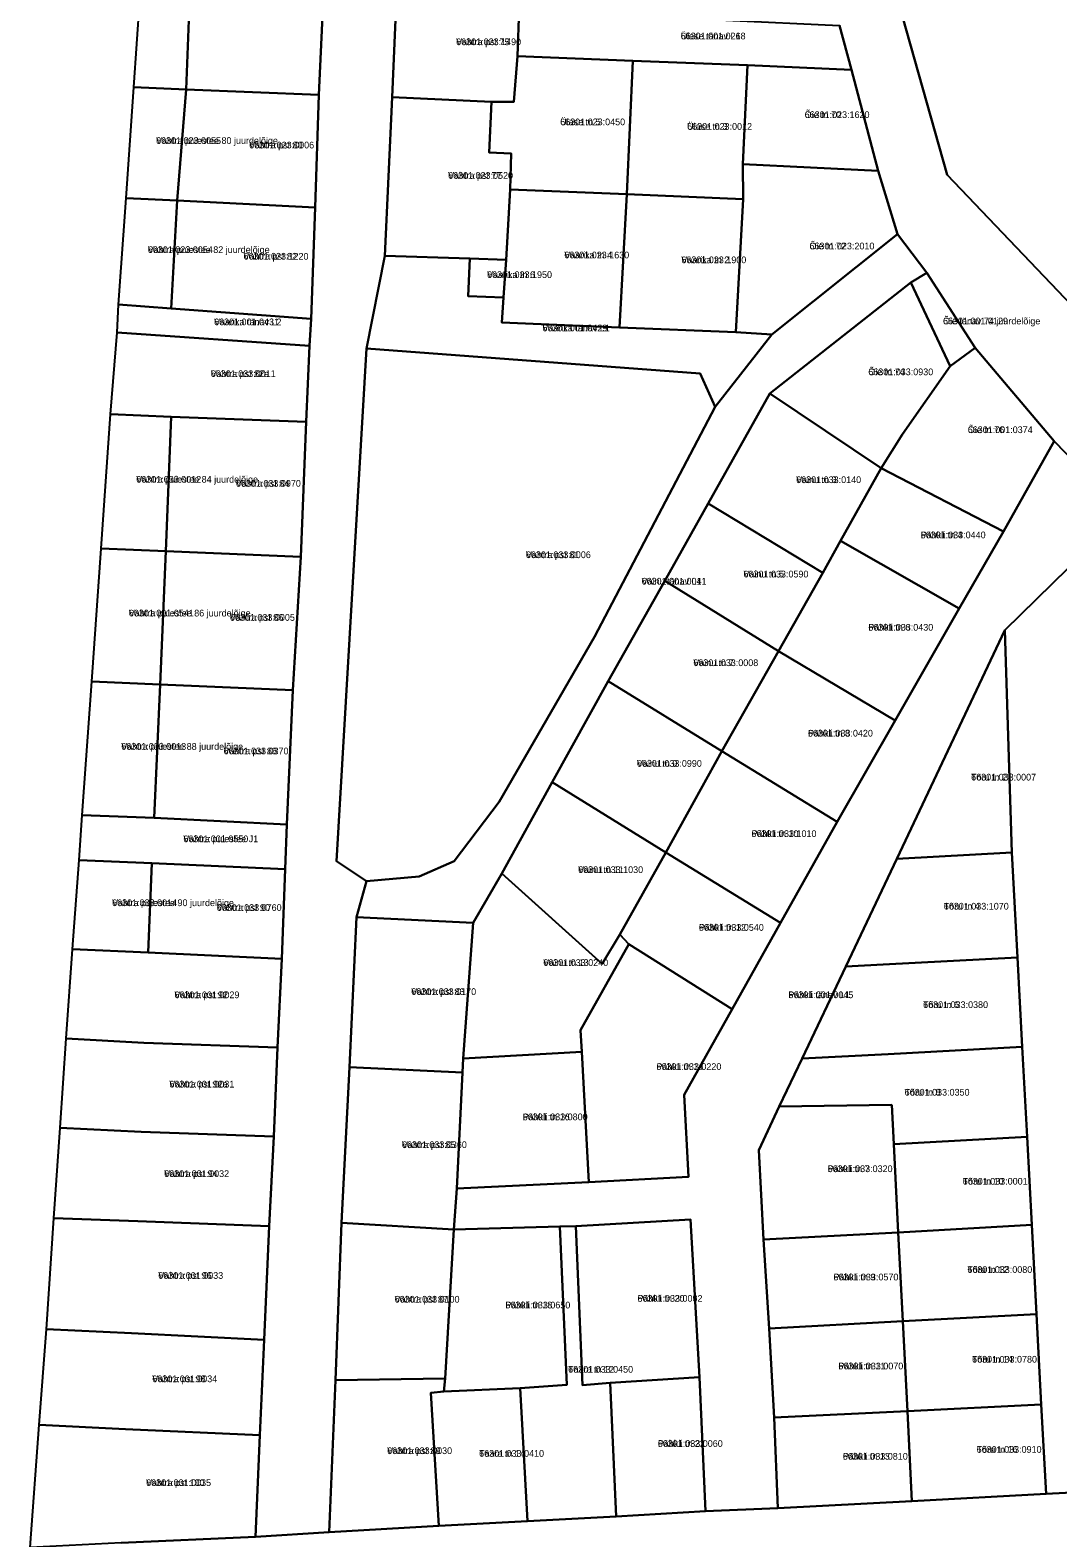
# Model space of a CAD drawing. Extents: x 632278 to 636344, y 6578401 to 6583362.
# Drawn here: x 633418.1 to 633647.7, y 6579191.1 to 6579527.9 of the extents above; entities that cross this region are included whole.
import ezdxf

# ---------------------------------------------------------------- set-up
doc = ezdxf.new("R2010")
doc.units = 0
for name, color, linetype in [('L_AADRESS', 7, 'Continuous'), ('PIIR', 7, 'Continuous'), ('TUNNUS', 7, 'Continuous')]:
    doc.layers.add(name, color=color, linetype=linetype)

msp = doc.modelspace()

# ---------------------------------------------------------------- linework, layer by layer
at = {"layer": 'PIIR'}
for points in [[(633731.62, 6579938.95), (633729.12, 6579898.18), (633727.06, 6579864.84), (633761.13, 6579852.59), (633767.01, 6579845.53), (633761.47, 6579821.43), (633754.84, 6579796.9), (633742.28, 6579739.12), (633736.02, 6579694.18), (633729.46, 6579605.05), (633719.19, 6579444.37), (633716.61, 6579430.7), (633712.76, 6579423.18), (633706.21, 6579417.63), (633697.14, 6579417.83), (633622.95, 6579495.56), (633611.14, 6579537.54), (633608.35, 6579581.69), (633605.51, 6579809.61), (633653.33, 6579978.24)], [(633500.02, 6579537.22), (633499.02, 6579512.94), (633497.4, 6579477.46), (633493.24, 6579456.8), (633486.56, 6579342.26), (633493.24, 6579337.75), (633491.03, 6579329.74), (633489.47, 6579296.23), (633487.68, 6579261.45), (633486.36, 6579226.34), (633484.92, 6579192.34), (633468.5, 6579191.32), (633469.42, 6579214.02), (633470.42, 6579235.35), (633471.5, 6579260.74), (633472.58, 6579280.76), (633473.39, 6579300.65), (633474.39, 6579320.44), (633475.08, 6579340.46), (633475.51, 6579350.45), (633476.83, 6579380.42), (633478.58, 6579410.22), (633479.79, 6579440.42), (633480.52, 6579457.36), (633480.9, 6579463.43), (633481.79, 6579488.29), (633482.64, 6579513.43), (633483.95, 6579542.35)], [(633611.14, 6579537.54), (633622.95, 6579495.56), (633697.14, 6579417.83), (633718.97, 6579394.93), (633711.9, 6579377.45), (633668.34, 6579418), (633662.27, 6579420.21), (633646.91, 6579436.06), (633629.25, 6579456.91), (633618.44, 6579473.7), (633611.88, 6579482.28), (633607.54, 6579496.46), (633601.63, 6579519.02), (633598.91, 6579528.9)], [(633650.04, 6579407.66), (633635.87, 6579393.82), (633611.74, 6579342.8), (633600.33, 6579318.69), (633590.6, 6579298.13), (633585.47, 6579287.42), (633580.93, 6579277.69), (633581.99, 6579257.71), (633583.2, 6579237.88), (633584.33, 6579217.94), (633585.14, 6579197.71), (633569, 6579197.03), (633567.65, 6579226.96), (633565.62, 6579262.21), (633540, 6579260.71), (633536.46, 6579260.63), (633512.76, 6579259.93), (633513.44, 6579269.1), (633542.91, 6579270.56), (633565.18, 6579271.75), (633564.21, 6579290.03), (633574.98, 6579309.21), (633585.77, 6579328.49), (633598.42, 6579351.03), (633611.36, 6579373.69), (633625.65, 6579398.67), (633635.54, 6579415.92), (633644.47, 6579431.82), (633646.91, 6579436.06), (633662.27, 6579420.21)], [(633438.5, 6579189.98), (633468.5, 6579191.32), (633484.92, 6579192.34), (633509.41, 6579193.75), (633529.26, 6579194.83), (633549.02, 6579195.85), (633569, 6579197.03), (633585.14, 6579197.71), (633615.1, 6579199.3), (633645.06, 6579200.89), (633661.04, 6579201.74), (633691, 6579203.33), (633720.95, 6579204.91), (633722.5, 6579190.62)]]:
    msp.add_lwpolyline(points, dxfattribs=at)
for points in [[(633443.32, 6579544.24), (633454.12, 6579543.73), (633452.98, 6579514.62), (633441.32, 6579515.15)], [(633454.12, 6579543.73), (633483.95, 6579542.35), (633482.64, 6579513.43), (633452.98, 6579514.62)], [(633500.02, 6579537.22), (633527.61, 6579536.52), (633527.39, 6579532.61), (633527.01, 6579522.04), (633526.21, 6579511.86), (633521.18, 6579511.84), (633499.02, 6579512.94)], [(633527.39, 6579532.61), (633550.35, 6579531.56), (633573.55, 6579530.08), (633598.91, 6579528.9), (633601.63, 6579519.02), (633578.37, 6579520.03), (633552.77, 6579521.04), (633527.01, 6579522.04)], [(633551.41, 6579491.24), (633525.35, 6579492.32), (633525.6, 6579500.36), (633520.71, 6579500.58), (633521.18, 6579511.84), (633526.21, 6579511.86), (633527.01, 6579522.04), (633552.77, 6579521.04)], [(633552.77, 6579521.04), (633578.37, 6579520.03), (633577.36, 6579497.94), (633577.39, 6579490.16), (633551.41, 6579491.24)], [(633601.63, 6579519.02), (633607.54, 6579496.46), (633577.36, 6579497.94), (633578.37, 6579520.03)], [(633441.32, 6579515.15), (633452.98, 6579514.62), (633450.97, 6579489.8), (633439.57, 6579490.33)], [(633450.97, 6579489.8), (633452.98, 6579514.62), (633482.64, 6579513.43), (633481.79, 6579488.29)], [(633499.02, 6579512.94), (633521.18, 6579511.84), (633520.71, 6579500.58), (633525.6, 6579500.36), (633525.35, 6579492.32), (633524.46, 6579476.6), (633516.32, 6579476.86), (633497.4, 6579477.46)], [(633575.79, 6579460.41), (633577.39, 6579490.16), (633577.36, 6579497.94), (633607.54, 6579496.46), (633611.88, 6579482.28), (633583.78, 6579459.87)], [(633523.9, 6579468.14), (633524.46, 6579476.6), (633525.35, 6579492.32), (633551.41, 6579491.24), (633549.82, 6579461.47), (633523.52, 6579462.54)], [(633439.57, 6579490.33), (633450.97, 6579489.8), (633449.66, 6579465.71), (633437.88, 6579466.57)], [(633449.66, 6579465.71), (633450.97, 6579489.8), (633481.79, 6579488.29), (633480.9, 6579463.43)], [(633551.41, 6579491.24), (633577.39, 6579490.16), (633575.79, 6579460.41), (633549.82, 6579461.47)], [(633611.88, 6579482.28), (633618.44, 6579473.7), (633614.85, 6579471.54), (633583.37, 6579446.75), (633569.58, 6579422.13), (633559.93, 6579404.83), (633547.23, 6579382.48), (633534.77, 6579359.89), (633523.52, 6579339.5), (633517.08, 6579328.49), (633491.03, 6579329.74), (633493.24, 6579337.75), (633505.06, 6579338.83), (633512.83, 6579342.26), (633522.93, 6579355.47), (633544.22, 6579392.32), (633571.19, 6579443.74), (633583.78, 6579459.87)], [(633497.4, 6579477.46), (633516.32, 6579476.86), (633515.96, 6579468.46), (633523.9, 6579468.14), (633523.52, 6579462.54), (633549.82, 6579461.47), (633575.79, 6579460.41), (633583.78, 6579459.87), (633571.19, 6579443.74), (633567.77, 6579451.21), (633493.24, 6579456.8)], [(633516.32, 6579476.86), (633524.46, 6579476.6), (633523.9, 6579468.14), (633515.96, 6579468.46)], [(633608.26, 6579430.06), (633583.37, 6579446.75), (633614.85, 6579471.54), (633623.64, 6579452.85), (633613, 6579437.61)], [(633614.85, 6579471.54), (633618.44, 6579473.7), (633629.25, 6579456.91), (633623.64, 6579452.85)], [(633437.88, 6579466.57), (633449.66, 6579465.71), (633480.9, 6579463.43), (633480.52, 6579457.36), (633437.55, 6579460.36)], [(633480.52, 6579457.36), (633479.79, 6579440.42), (633449.65, 6579441.53), (633436.08, 6579442.07), (633437.55, 6579460.36)], [(633493.24, 6579456.8), (633567.77, 6579451.21), (633571.19, 6579443.74), (633544.22, 6579392.32), (633522.93, 6579355.47), (633512.83, 6579342.26), (633505.06, 6579338.83), (633493.24, 6579337.75), (633486.56, 6579342.26)], [(633623.64, 6579452.85), (633629.25, 6579456.91), (633646.91, 6579436.06), (633644.47, 6579431.82), (633635.54, 6579415.92), (633608.26, 6579430.06), (633613, 6579437.61)], [(633608.26, 6579430.06), (633599.17, 6579413.79), (633595.18, 6579406.65), (633569.58, 6579422.13), (633583.37, 6579446.75)], [(633436.08, 6579442.07), (633449.65, 6579441.53), (633448.42, 6579411.46), (633434.02, 6579412.07)], [(633448.42, 6579411.46), (633449.65, 6579441.53), (633479.79, 6579440.42), (633478.58, 6579410.22)], [(633608.26, 6579430.06), (633635.54, 6579415.92), (633625.65, 6579398.67), (633599.17, 6579413.79)], [(633569.58, 6579422.13), (633595.18, 6579406.65), (633585.32, 6579389.12), (633559.93, 6579404.83)], [(633448.42, 6579411.46), (633447.21, 6579381.68), (633431.94, 6579382.38), (633434.02, 6579412.07)], [(633448.42, 6579411.46), (633478.58, 6579410.22), (633476.83, 6579380.42), (633447.21, 6579381.68)], [(633595.18, 6579406.65), (633599.17, 6579413.79), (633625.65, 6579398.67), (633611.36, 6579373.69), (633585.32, 6579389.12)], [(633635.87, 6579393.82), (633650.04, 6579407.66), (633650.83, 6579391.32), (633652.84, 6579361.34), (633654.02, 6579341.46), (633654.99, 6579321.67), (633656.02, 6579301.75), (633656.78, 6579281.63), (633657.84, 6579261.66), (633658.91, 6579241.68), (633659.97, 6579221.71), (633661.04, 6579201.74), (633645.06, 6579200.89), (633644, 6579220.86), (633642.96, 6579241.06), (633641.89, 6579261.03), (633640.82, 6579280.65), (633639.73, 6579300.75), (633638.67, 6579320.73), (633637.42, 6579344.17)], [(633559.93, 6579404.83), (633585.32, 6579389.12), (633572.61, 6579366.8), (633547.23, 6579382.48)], [(633635.87, 6579393.82), (633637.42, 6579344.17), (633611.74, 6579342.8)], [(633611.36, 6579373.69), (633598.42, 6579351.03), (633572.61, 6579366.8), (633585.32, 6579389.12)], [(633431.94, 6579382.38), (633447.21, 6579381.68), (633445.87, 6579351.89), (633429.78, 6579352.5)], [(633476.83, 6579380.42), (633475.51, 6579350.45), (633445.87, 6579351.89), (633447.21, 6579381.68)], [(633547.23, 6579382.48), (633572.61, 6579366.8), (633560.11, 6579344.16), (633534.77, 6579359.89)], [(633572.61, 6579366.8), (633598.42, 6579351.03), (633585.77, 6579328.49), (633560.11, 6579344.16)], [(633549.83, 6579325.87), (633545.91, 6579319.3), (633523.52, 6579339.5), (633534.77, 6579359.89), (633560.11, 6579344.16)], [(633475.51, 6579350.45), (633475.08, 6579340.46), (633445.31, 6579341.82), (633429.11, 6579342.49), (633429.78, 6579352.5), (633445.87, 6579351.89)], [(633549.83, 6579325.87), (633560.11, 6579344.16), (633585.77, 6579328.49), (633574.98, 6579309.21), (633551.87, 6579323.69)], [(633600.33, 6579318.69), (633611.74, 6579342.8), (633637.42, 6579344.17), (633638.67, 6579320.73), (633608.71, 6579319.13)], [(633429.11, 6579342.49), (633445.31, 6579341.82), (633444.47, 6579321.86), (633427.59, 6579322.62)], [(633445.31, 6579341.82), (633475.08, 6579340.46), (633474.39, 6579320.44), (633444.47, 6579321.86)], [(633517.08, 6579328.49), (633523.52, 6579339.5), (633545.91, 6579319.3), (633549.83, 6579325.87), (633551.87, 6579323.69), (633541.1, 6579304.51), (633541.36, 6579299.63), (633514.9, 6579298.17)], [(633514.9, 6579298.17), (633514.68, 6579295.03), (633489.47, 6579296.23), (633491.03, 6579329.74), (633517.08, 6579328.49)], [(633541.36, 6579299.63), (633541.1, 6579304.51), (633551.87, 6579323.69), (633574.98, 6579309.21), (633564.21, 6579290.03), (633565.18, 6579271.75), (633542.91, 6579270.56)], [(633426.18, 6579302.6), (633427.59, 6579322.62), (633444.47, 6579321.86), (633474.39, 6579320.44), (633473.39, 6579300.65), (633443.57, 6579301.66)], [(633590.6, 6579298.13), (633600.33, 6579318.69), (633608.71, 6579319.13), (633638.67, 6579320.73), (633639.73, 6579300.75), (633609.77, 6579299.16)], [(633424.86, 6579282.64), (633426.18, 6579302.6), (633443.57, 6579301.66), (633473.39, 6579300.65), (633472.58, 6579280.76), (633442.93, 6579281.75)], [(633514.68, 6579295.03), (633514.9, 6579298.17), (633541.36, 6579299.63), (633542.91, 6579270.56), (633513.44, 6579269.1)], [(633610.63, 6579287.84), (633585.47, 6579287.42), (633590.6, 6579298.13), (633609.77, 6579299.16), (633639.73, 6579300.75), (633640.82, 6579280.65), (633611.09, 6579278.99)], [(633489.47, 6579296.23), (633514.68, 6579295.03), (633513.44, 6579269.1), (633512.76, 6579259.93), (633487.68, 6579261.45)], [(633610.63, 6579287.84), (633611.09, 6579278.99), (633612.01, 6579259.3), (633581.99, 6579257.71), (633580.93, 6579277.69), (633585.47, 6579287.42)], [(633423.4, 6579262.52), (633424.86, 6579282.64), (633442.93, 6579281.75), (633472.58, 6579280.76), (633471.5, 6579260.74), (633442.18, 6579261.8)], [(633640.82, 6579280.65), (633641.89, 6579261.03), (633612.01, 6579259.3), (633611.09, 6579278.99)], [(633421.78, 6579237.68), (633423.4, 6579262.52), (633442.18, 6579261.8), (633471.5, 6579260.74), (633470.42, 6579235.35), (633440.78, 6579236.78)], [(633487.68, 6579261.45), (633512.76, 6579259.93), (633510.86, 6579226.68), (633486.36, 6579226.34)], [(633510.86, 6579226.68), (633512.76, 6579259.93), (633536.46, 6579260.63), (633538.03, 6579225.24), (633527.61, 6579224.52), (633510.57, 6579223.8)], [(633527.61, 6579224.52), (633538.03, 6579225.24), (633536.46, 6579260.63), (633540, 6579260.71), (633541.52, 6579225.17), (633547.7, 6579225.74), (633549.02, 6579195.85), (633529.26, 6579194.83)], [(633565.62, 6579262.21), (633567.65, 6579226.96), (633547.7, 6579225.74), (633541.52, 6579225.17), (633540, 6579260.71)], [(633581.99, 6579257.71), (633612.01, 6579259.3), (633613.11, 6579239.48), (633583.2, 6579237.88)], [(633612.01, 6579259.3), (633641.89, 6579261.03), (633642.96, 6579241.06), (633613.11, 6579239.48)], [(633613.11, 6579239.48), (633614.11, 6579219.38), (633584.33, 6579217.94), (633583.2, 6579237.88)], [(633613.11, 6579239.48), (633642.96, 6579241.06), (633644, 6579220.86), (633614.11, 6579219.38)], [(633420.14, 6579216.36), (633421.78, 6579237.68), (633440.78, 6579236.78), (633470.42, 6579235.35), (633469.42, 6579214.02), (633439.45, 6579215.39)], [(633486.36, 6579226.34), (633510.86, 6579226.68), (633510.57, 6579223.8), (633507.61, 6579223.5), (633509.41, 6579193.75), (633484.92, 6579192.34)], [(633567.65, 6579226.96), (633569, 6579197.03), (633549.02, 6579195.85), (633547.7, 6579225.74)], [(633507.61, 6579223.5), (633510.57, 6579223.8), (633527.61, 6579224.52), (633529.26, 6579194.83), (633509.41, 6579193.75)], [(633584.33, 6579217.94), (633614.11, 6579219.38), (633615.1, 6579199.3), (633585.14, 6579197.71)], [(633614.11, 6579219.38), (633644, 6579220.86), (633645.06, 6579200.89), (633615.1, 6579199.3)], [(633418.14, 6579188.93), (633420.14, 6579216.36), (633439.45, 6579215.39), (633469.42, 6579214.02), (633468.5, 6579191.32), (633438.5, 6579189.98)]]:
    msp.add_lwpolyline(points, close=True, dxfattribs=at)

# ---------------------------------------------------------------- texts
at = {"layer": 'L_AADRESS'}
for s, p in [('Vahtra pst 75', (633513.3, 6579524.53)), ('Ülase tänav L1', (633563.45, 6579525.82)), ('Ülase tn 5', (633536.54, 6579506.64)), ('Õie tn 70', (633591.14, 6579508.25)), ('Ülase tn 3', (633564.89, 6579505.62)), ('Vahtra puiestee 80 juurdelõige', (633446.27, 6579502.47)), ('Vahtra pst 80', (633467.07, 6579501.46)), ('Vahtra pst 77', (633511.5, 6579494.67)), ('Vahtra puiestee 82 juurdelõige', (633444.43, 6579478.1)), ('Vahtra pst 82', (633465.81, 6579476.62)), ('Vaarika tn 4', (633537.46, 6579476.9)), ('Õie tn 72', (633592.22, 6579478.91)), ('Vaarika tn 2', (633563.61, 6579475.82)), ('Vaarika tn 6', (633520.21, 6579472.51)), ('Vaarika tänav L2', (633459.22, 6579461.96)), ('Vaarika tänav L1', (633532.57, 6579460.6)), ('Õie tänav 74 juurdelõige', (633622.05, 6579462.16)), ('Vahtra pst 82a', (633458.48, 6579450.39)), ('Õie tn 74', (633605.36, 6579450.8)), ('Õie tn 76', (633627.58, 6579437.87)), ('Vahtra puiestee 84 juurdelõige', (633441.84, 6579426.79)), ('Vahtra pst 84', (633464.11, 6579425.88)), ('Vainu tn 3', (633589.26, 6579426.7)), ('Pähkli tn 4', (633617.07, 6579414.37)), ('Vahtra pst 81', (633528.88, 6579409.94)), ('Vainu tn 5', (633577.49, 6579405.62)), ('Vainu tänav L1', (633554.73, 6579404.03)), ('Vahtra puiestee 86 juurdelõige', (633440.18, 6579396.91)), ('Vahtra pst 86', (633462.77, 6579395.94)), ('Pähkli tn 6', (633605.37, 6579393.74)), ('Vainu tn 7', (633566.28, 6579385.82)), ('Pähkli tn 8', (633591.89, 6579370.08)), ('Vahtra puiestee 88 juurdelõige', (633438.5, 6579367.12)), ('Vahtra pst 88', (633461.35, 6579366.11)), ('Vainu tn 9', (633553.68, 6579363.32)), ('Tõru tn 2', (633628.34, 6579360.26)), ('Vahtra puiestee J1', (633452.36, 6579346.48)), ('Pähkli tn 10', (633579.28, 6579347.65)), ('Vainu tn 11', (633540.56, 6579339.6)), ('Vahtra puiestee 90 juurdelõige', (633436.45, 6579332.2)), ('Vahtra pst 90', (633459.81, 6579331.13)), ('Tõru tn 4', (633622.23, 6579331.43)), ('Pähkli tn 12', (633567.52, 6579326.69)), ('Vainu tn 13', (633532.76, 6579318.84)), ('Vahtra pst 92', (633450.38, 6579311.63)), ('Vahtra pst 83', (633503.27, 6579312.36)), ('Pähkli tänav L1', (633587.52, 6579311.64)), ('Tõru tn 6', (633617.61, 6579309.43)), ('Pähkli tn 14', (633558.04, 6579295.6)), ('Vahtra pst 92a', (633449.24, 6579291.68)), ('Tõru tn 8', (633613.48, 6579289.87)), ('Pähkli tn 16', (633528.17, 6579284.37)), ('Vahtra pst 85', (633501.18, 6579278.15)), ('Vahtra pst 94', (633448.08, 6579271.69)), ('Pähkli tn 7', (633596.29, 6579272.78)), ('Tõru tn 10', (633626.46, 6579269.98)), ('Vahtra pst 96', (633446.76, 6579248.94)), ('Pähkli tn 9', (633597.58, 6579248.59)), ('Tõru tn 12', (633627.49, 6579250.26)), ('Vahtra pst 87', (633499.56, 6579243.63)), ('Pähkli tn 18', (633524.3, 6579242.33)), ('Pähkli tn 20', (633553.82, 6579243.82)), ('Taara tn 12', (633538.32, 6579227.98)), ('Pähkli tn 11', (633598.68, 6579228.71)), ('Tõru tn 14', (633628.54, 6579230.22)), ('Vahtra pst 98', (633445.42, 6579225.85)), ('Pähkli tn 22', (633558.35, 6579211.4)), ('Vahtra pst 89', (633497.89, 6579209.79)), ('Taara tn 14', (633518.43, 6579209.19)), ('Pähkli tn 13', (633599.68, 6579208.54)), ('Tõru tn 16', (633629.57, 6579210.08)), ('Vahtra pst 100', (633444.05, 6579202.65))]:
    msp.add_text(s, height=1.5, dxfattribs=at).set_placement(p)
at = {"layer": 'TUNNUS'}
for s, p in [('66301:023:1490', (633513.3, 6579524.53)), ('66301:001:0268', (633563.45, 6579525.82)), ('66301:023:1620', (633591.14, 6579508.25)), ('66301:023:0450', (633536.54, 6579506.64)), ('66301:023:0012', (633564.89, 6579505.62)), ('66301:023:0055', (633446.27, 6579502.47)), ('66301:023:0006', (633467.07, 6579501.46)), ('66301:023:0520', (633511.5, 6579494.67)), ('66301:023:0054', (633444.43, 6579478.1)), ('66301:023:1220', (633465.81, 6579476.62)), ('66301:023:1630', (633537.46, 6579476.9)), ('66301:023:2010', (633592.22, 6579478.91)), ('66301:023:1900', (633563.61, 6579475.82)), ('66301:023:1950', (633520.21, 6579472.51)), ('66301:001:0431', (633459.22, 6579461.96)), ('66301:001:0429', (633532.57, 6579460.6)), ('66301:001:0129', (633622.05, 6579462.16)), ('66301:033:0011', (633458.48, 6579450.39)), ('66301:033:0930', (633605.36, 6579450.8)), ('66301:001:0374', (633627.58, 6579437.87)), ('66301:033:0012', (633441.84, 6579426.79)), ('66301:033:0970', (633464.11, 6579425.88)), ('66301:033:0140', (633589.26, 6579426.7)), ('66301:033:0440', (633617.07, 6579414.37)), ('66301:033:0006', (633528.88, 6579409.94)), ('66301:001:0041', (633554.73, 6579404.03)), ('66301:033:0590', (633577.49, 6579405.62)), ('66301:001:0541', (633440.18, 6579396.91)), ('66301:033:0005', (633462.77, 6579395.94)), ('66301:033:0430', (633605.37, 6579393.74)), ('66301:033:0008', (633566.28, 6579385.82)), ('66301:033:0420', (633591.89, 6579370.08)), ('66301:033:0013', (633438.5, 6579367.12)), ('66301:033:0370', (633461.35, 6579366.11)), ('66301:033:0990', (633553.68, 6579363.32)), ('66301:033:0007', (633628.34, 6579360.26)), ('66301:001:0550', (633452.36, 6579346.48)), ('66301:033:1010', (633579.28, 6579347.65)), ('66301:033:1030', (633540.56, 6579339.6)), ('66301:033:0014', (633436.45, 6579332.2)), ('66301:033:0760', (633459.81, 6579331.13)), ('66301:033:1070', (633622.23, 6579331.43)), ('66301:033:0540', (633567.52, 6579326.69)), ('66301:033:0240', (633532.76, 6579318.84)), ('66301:001:0029', (633450.38, 6579311.63)), ('66301:033:0170', (633503.27, 6579312.36)), ('66301:001:0045', (633587.52, 6579311.64)), ('66301:033:0380', (633617.61, 6579309.43)), ('66301:033:0220', (633558.04, 6579295.6)), ('66301:001:0031', (633449.24, 6579291.68)), ('66301:033:0350', (633613.48, 6579289.87)), ('66301:033:0800', (633528.17, 6579284.37)), ('66301:033:0360', (633501.18, 6579278.15)), ('66301:001:0032', (633448.08, 6579271.69)), ('66301:033:0320', (633596.29, 6579272.78)), ('66301:033:0001', (633626.46, 6579269.98)), ('66301:001:0033', (633446.76, 6579248.94)), ('66301:033:0570', (633597.58, 6579248.59)), ('66301:033:0080', (633627.49, 6579250.26)), ('66301:033:0100', (633499.56, 6579243.63)), ('66301:033:0650', (633524.3, 6579242.33)), ('66301:033:0002', (633553.82, 6579243.82)), ('66301:033:0450', (633538.32, 6579227.98)), ('66301:033:0070', (633598.68, 6579228.71)), ('66301:033:0780', (633628.54, 6579230.22)), ('66301:001:0034', (633445.42, 6579225.85)), ('66301:033:0060', (633558.35, 6579211.4)), ('66301:033:0030', (633497.89, 6579209.79)), ('66301:033:0410', (633518.43, 6579209.19)), ('66301:033:0810', (633599.68, 6579208.54)), ('66301:033:0910', (633629.57, 6579210.08)), ('66301:001:0035', (633444.05, 6579202.65))]:
    msp.add_text(s, height=1.5, dxfattribs=at).set_placement(p)

doc.saveas('drawing.dxf')
